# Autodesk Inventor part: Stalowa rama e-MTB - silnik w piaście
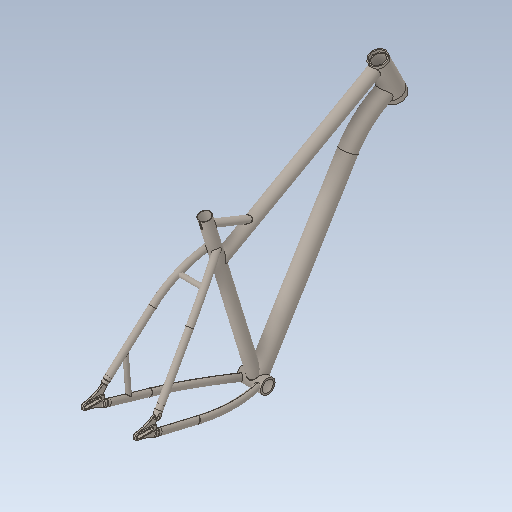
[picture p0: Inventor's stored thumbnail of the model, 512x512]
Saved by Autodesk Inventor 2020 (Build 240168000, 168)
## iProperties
Created: 2017-09
Part Number: Stalowa rama e-MTB - silnik w piaście
Material: solidworks materials|AISI 4130 Stal odprężona w 865C|94
Document SubType Name: Modeling
Designer: Tomasz
Density: 7.85 g/cm^3
Appearance: 166,158,150
Sending System: SolidWorks 2017
Last Author: Tomasz
Last Saved: 2017-11-19
Author: Tomasz
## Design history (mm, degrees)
combine "Extrude-Thin1"
combine "Revolve1"
combine "Przytnij_Wydłuż9"
combine "Bike frame tubing SEAT STAY 0.48 X 0.55 INCH(1)[2]"
combine "_DS0050_-_Imported1_"
combine "_DS0004BD_1_-_Chamfer2_"
combine "_DS0004_1_-_Chamfer2_"
combine "Przytnij_Wydłuż21"
combine "Combine1"
combine "Combine3"
combine "Combine4"
combine "Combine5"
combine "Combine6"
combine "Combine7"
combine "Przytnij_Wydłuż25"
node "Bryła1"
node "Bryła2"
node "Bryła3"
node "Bryła4"
node "Bryła5"
node "Bryła6"
node "Bryła7"
node "Bryła8"
node "Bryła9"
node "Bryła10"
node "Bryła11"
node "Bryła12"
node "Bryła13"
node "Bryła14"
node "Bryła15"
